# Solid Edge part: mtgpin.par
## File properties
Document Number: MP-101
Revision: 1
Project Name: Trolley Wheel Assembly
File Size: 0
Number of Sheets: 0
Number of Objects: 0
Title: Mounting Pin
Subject: Carrier Assembly
Author: Dwight Yorke
Keywords: Mounting Pin
Comments: Mounting Pin
Template: metric.par
Last saved by: rkriggs
Revision: 50
Application: Solid Edge
Category: Macined Cylindrical
Manager: Brian Little
Company: Wheels R Us
Density: 8906
Accuracy: 0.99
Material: Copper
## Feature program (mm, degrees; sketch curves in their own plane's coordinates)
sketch for "unnamed RevolvedProtrusion 1" plane through (0, 0, 0) normal (0, -1, 0) x-axis (1, 0, 0)
  line (-56.4485, 0) -> (-56.4485, 10.25)
  line (-56.4485, 10.25) -> (-6.4485, 10.25)
  line (-6.4485, 10.25) -> (-6.4485, 18)
  line (-6.4485, 18) -> (5.5515, 18)
  line (5.5515, 18) -> (5.5515, 0)
  line (5.5515, 0) -> (-56.4485, 0)
revolve "unnamed RevolvedProtrusion 1" add finite 360 deg about sketch line (21.325, 0) -> (44.5316, 0)
sketch for "unnamed Cutout 1" plane through (0, 0, 0) normal (0, -1, 0) x-axis (1, 0, 0)
extrude "unnamed Cutout 1" cut through
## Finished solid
Body 1: solid body, 9 faces, 15 edges, 8 vertices.
  Faces by surface: plane 7, cylinder 2
  Edges by curve: line 8, circle 7
Bounding box of the edges (mm): 62.000 x 36.000 x 36.000, from (-56.4485, -18, -18) to (5.5515, 18, 18).
Cylindrical faces by radius (mm): R10.25 x1, R18 x1
Planar faces by outward normal: +x 3, +z 1, -x 2, -z 1
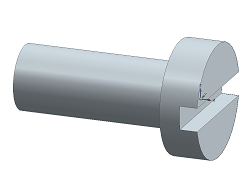
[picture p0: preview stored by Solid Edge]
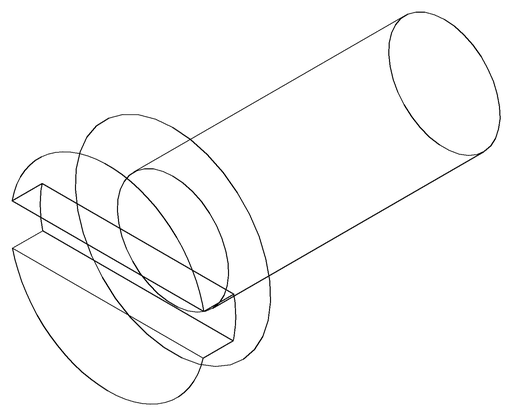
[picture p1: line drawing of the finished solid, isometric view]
